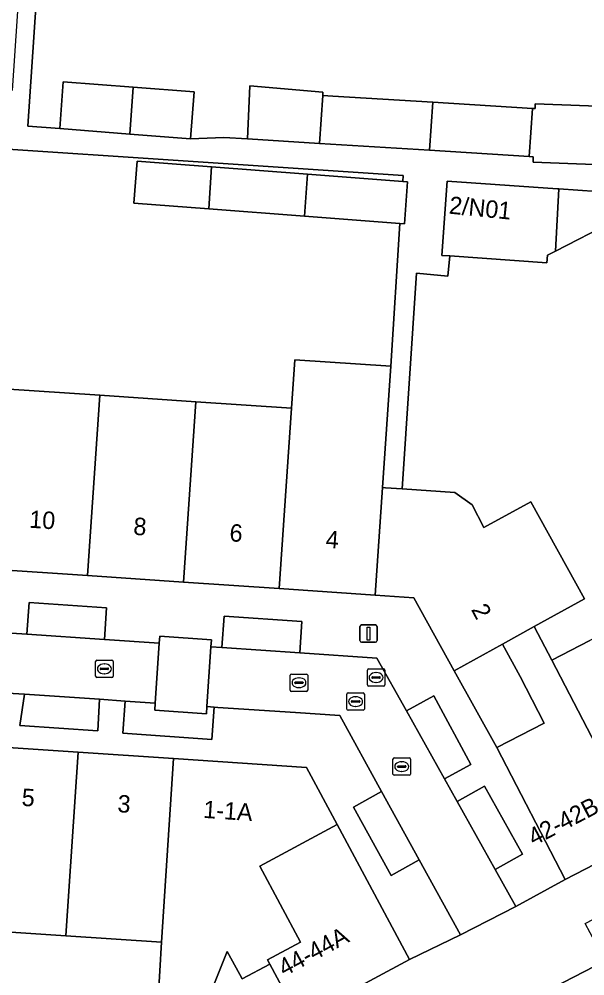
# Model space of a CAD drawing. Extents: x 159960 to 160866, y 382700 to 383354.
# Drawn here: x 160719.9 to 160752.4, y 382866.2 to 382921.1 of the extents above; entities that cross this region are included whole.
import ezdxf

# ---------------------------------------------------------------- set-up
doc = ezdxf.new("R2010")
doc.units = 0
for name, color, linetype in [('IMGEO_Erf', 7, 'Continuous'), ('IMGEO_Kolk', 7, 'Continuous'), ('IMGEO_Lichtmast', 7, 'Continuous'), ('IMGEO_Muur', 7, 'Continuous'), ('IMGEO_Pand', 7, 'Continuous'), ('IMGEO_Pand_nummerreeks', 7, 'Continuous'), ('IMGEO_Parkeervlak_open', 7, 'Continuous'), ('IMGEO_Rijbaan_lokaal_gesloten', 7, 'Continuous'), ('IMGEO_Rijbaan_lokaal_open', 7, 'Continuous'), ('IMGEO_Rioolput', 7, 'Continuous'), ('IMGEO_Voetpad_open', 7, 'Continuous')]:
    doc.layers.add(name, color=color, linetype=linetype)

msp = doc.modelspace()

# ---------------------------------------------------------------- linework, layer by layer
at = {"layer": 'IMGEO_Erf'}
for points in [[(160721.141, 382925.437), (160720.441, 382914.914), (160722.268, 382914.773), (160722.468, 382917.457), (160726.471, 382917.147), (160729.977, 382916.876), (160729.769, 382914.193), (160731.671, 382914.265), (160733.035, 382914.18), (160733.162, 382917.224), (160737.357, 382916.868), (160737.36, 382916.674), (160737.931, 382916.639), (160743.655, 382916.287), (160749.378, 382915.935), (160749.531, 382915.926), (160749.541, 382916.192), (160755.128, 382915.981)], [(160719.066, 382899.852), (160724.562, 382899.48), (160730.062, 382899.107), (160735.56, 382898.735), (160735.748, 382901.514), (160741.247, 382901.143), (160741.781, 382909.327), (160736.304, 382909.749), (160730.811, 382910.171), (160726.522, 382910.501), (160726.707, 382912.909), (160730.974, 382912.581), (160736.468, 382912.159), (160741.938, 382911.739), (160741.961, 382912.089), (160705.794, 382914.494)], [(160753.972, 382909.417), (160750.694, 382907.746), (160750.235, 382907.512), (160750.204, 382907.077), (160744.632, 382907.467), (160744.527, 382906.317), (160742.735, 382906.48), (160741.896, 382894.101), (160744.934, 382893.895), (160745.914, 382893.187), (160746.593, 382891.885), (160749.282, 382893.367), (160752.358, 382887.787), (160749.477, 382886.199), (160750.483, 382884.269), (160752.675, 382885.402)], [(160727.919, 382864.809), (160728.103, 382868.092), (160722.617, 382868.458), (160717.143, 382868.823), (160711.667, 382869.188), (160706.193, 382869.553), (160700.717, 382869.918), (160695.243, 382870.283), (160689.627, 382870.657), (160689.38, 382863.428)], [(160735.99, 382863.702), (160734.309, 382866.839), (160732.737, 382865.996), (160732.604, 382866.237), (160731.87, 382867.558), (160730.719, 382864.693)]]:
    msp.add_lwpolyline(points, dxfattribs=at)
msp.add_lwpolyline([(160747.334, 382879.263), (160750.054, 382880.669), (160748.677, 382883.335), (160747.652, 382885.194), (160744.889, 382883.671)], close=True, dxfattribs=at)
at = {"layer": 'IMGEO_Kolk'}
for p, q in [((160724.323, 382883.353), (160724.323, 382884.205)), ((160724.398, 382884.279), (160725.25, 382884.279)), ((160725.324, 382884.205), (160725.324, 382883.353)), ((160724.582, 382883.773), (160724.582, 382883.785)), ((160725.02, 382883.736), (160724.622, 382883.736)), ((160724.625, 382883.822), (160725.023, 382883.822)), ((160724.811, 382884.059), (160724.836, 382884.059)), ((160725.066, 382883.785), (160725.066, 382883.773)), ((160725.25, 382883.279), (160724.398, 382883.279)), ((160724.834, 382883.499), (160724.809, 382883.499)), ((160735.487, 382882.555), (160735.487, 382883.407)), ((160735.562, 382883.481), (160736.414, 382883.481)), ((160735.975, 382883.261), (160736, 382883.261)), ((160736.488, 382883.407), (160736.488, 382882.555)), ((160735.746, 382882.975), (160735.746, 382882.987)), ((160736.184, 382882.938), (160735.786, 382882.938)), ((160735.789, 382883.024), (160736.187, 382883.024)), ((160735.998, 382882.701), (160735.973, 382882.701)), ((160736.23, 382882.987), (160736.23, 382882.975)), ((160736.414, 382882.481), (160735.562, 382882.481)), ((160741.454, 382878.67), (160742.306, 382878.67)), ((160741.379, 382877.744), (160741.379, 382878.596)), ((160741.638, 382878.164), (160741.638, 382878.176)), ((160742.076, 382878.127), (160741.678, 382878.127)), ((160741.681, 382878.213), (160742.079, 382878.213)), ((160741.867, 382878.45), (160741.892, 382878.45)), ((160742.122, 382878.176), (160742.122, 382878.164)), ((160742.38, 382878.596), (160742.38, 382877.744)), ((160742.306, 382877.67), (160741.454, 382877.67)), ((160741.89, 382877.89), (160741.865, 382877.89))]:
    msp.add_line(p, q, dxfattribs=at)
for points in [[(160724.323, 382883.353), (160724.323, 382884.205)], [(160724.398, 382884.279), (160725.25, 382884.279)], [(160725.324, 382884.205), (160725.324, 382883.353)], [(160725.25, 382883.279), (160724.398, 382883.279)], [(160735.487, 382882.555), (160735.487, 382883.407)], [(160735.562, 382883.481), (160736.414, 382883.481)], [(160736.488, 382883.407), (160736.488, 382882.555)], [(160736.414, 382882.481), (160735.562, 382882.481)], [(160741.454, 382878.67), (160742.306, 382878.67)], [(160741.379, 382877.744), (160741.379, 382878.596)], [(160742.38, 382878.596), (160742.38, 382877.744)], [(160742.306, 382877.67), (160741.454, 382877.67)]]:
    msp.add_lwpolyline(points, dxfattribs=at)
for centre, radius, start, end in [((160724.4, 382884.203), 0.0765, 91.552, 178.448), ((160724.4, 382884.203), 0.0765, 91.552, 178.448), ((160725.248, 382884.203), 0.0765, 1.552, 88.448), ((160725.248, 382884.203), 0.0765, 1.552, 88.448), ((160724.622, 382883.782), 0.0403, 85.8775, 175.7526), ((160724.619, 382883.772), 0.0366, 178.938, 274.7102), ((160725.023, 382883.779), 0.043, 264.8664, 352.4533), ((160725.027, 382883.784), 0.0386, 1.7309, 96.639), ((160724.4, 382883.355), 0.0765, 181.552, 268.448), ((160724.4, 382883.355), 0.0765, 181.552, 268.448), ((160725.248, 382883.355), 0.0765, 271.552, 358.448), ((160725.248, 382883.355), 0.0765, 271.552, 358.448), ((160735.564, 382883.405), 0.0765, 91.552, 178.448), ((160735.564, 382883.405), 0.0765, 91.552, 178.448), ((160736.412, 382883.405), 0.0765, 1.552, 88.448), ((160736.412, 382883.405), 0.0765, 1.552, 88.448), ((160735.564, 382882.557), 0.0765, 181.552, 268.448), ((160735.564, 382882.557), 0.0765, 181.552, 268.448), ((160735.786, 382882.984), 0.0403, 85.8775, 175.7526), ((160735.783, 382882.974), 0.0366, 178.938, 274.7102), ((160736.187, 382882.981), 0.043, 264.8664, 352.4533), ((160736.191, 382882.986), 0.0386, 1.7309, 96.639), ((160736.412, 382882.557), 0.0765, 271.552, 358.448), ((160736.412, 382882.557), 0.0765, 271.552, 358.448), ((160741.456, 382878.594), 0.0765, 91.552, 178.448), ((160741.456, 382878.594), 0.0765, 91.552, 178.448), ((160742.304, 382878.594), 0.0765, 1.552, 88.448), ((160742.304, 382878.594), 0.0765, 1.552, 88.448), ((160741.678, 382878.173), 0.0403, 85.8775, 175.7526), ((160741.675, 382878.163), 0.0366, 178.938, 274.7102), ((160742.079, 382878.17), 0.043, 264.8664, 352.4533), ((160742.083, 382878.175), 0.0386, 1.7309, 96.639), ((160741.456, 382877.746), 0.0765, 181.552, 268.448), ((160741.456, 382877.746), 0.0765, 181.552, 268.448), ((160742.304, 382877.746), 0.0765, 271.552, 358.448), ((160742.304, 382877.746), 0.0765, 271.552, 358.448)]:
    msp.add_arc(centre, radius, start, end, dxfattribs=at)
for centre, major_axis, ratio, start_param, end_param in [((160724.81, 382883.779), (-0.387, 0.002), 0.722429, 4.712389, 7.853982), ((160724.835, 382883.779), (-0.39, 0.002), 0.717154, 1.570796, 4.712389), ((160735.974, 382882.981), (-0.387, 0.002), 0.722429, 4.712389, 7.853982), ((160735.999, 382882.981), (-0.39, 0.002), 0.717154, 1.570796, 4.712389), ((160741.866, 382878.17), (-0.387, 0.002), 0.722429, 4.712389, 7.853982), ((160741.891, 382878.17), (-0.39, 0.002), 0.717154, 1.570796, 4.712389)]:
    msp.add_ellipse(centre, major_axis=major_axis, ratio=ratio, start_param=start_param, end_param=end_param, dxfattribs=at)
at = {"layer": 'IMGEO_Lichtmast'}
for p, q in [((160739.481, 382885.401), (160739.481, 382886.201)), ((160739.481, 382886.201), (160739.481, 382885.401)), ((160739.581, 382886.301), (160740.371, 382886.301)), ((160740.371, 382886.301), (160739.581, 382886.301)), ((160740.471, 382886.201), (160740.471, 382885.401)), ((160740.471, 382885.401), (160740.471, 382886.201)), ((160740.371, 382885.301), (160739.581, 382885.301)), ((160739.581, 382885.301), (160740.371, 382885.301))]:
    msp.add_line(p, q, dxfattribs=at)
msp.add_lwpolyline([(160739.901, 382886.176), (160740.051, 382886.176), (160740.051, 382885.426), (160739.901, 382885.426), (160739.901, 382886.176)], dxfattribs=at)
for centre, start, end in [((160739.581, 382886.201), 90, 180), ((160739.581, 382886.201), 90, 180), ((160740.371, 382886.201), 0, 90), ((160740.371, 382886.201), 360, 90), ((160739.581, 382885.401), 180, 270), ((160739.581, 382885.401), 180, 270), ((160740.371, 382885.401), 270, 0), ((160740.371, 382885.401), 270, 0)]:
    msp.add_arc(centre, 0.1, start, end, dxfattribs=at)
at = {"layer": 'IMGEO_Muur'}
msp.add_lwpolyline([(160744.889, 382883.671), (160747.334, 382879.263)], dxfattribs=at)
at = {"layer": 'IMGEO_Pand'}
for points in [[(160726.471, 382917.147), (160722.468, 382917.457), (160722.268, 382914.773), (160726.287, 382914.462)], [(160726.471, 382917.147), (160726.287, 382914.462), (160729.769, 382914.193), (160729.977, 382916.876)], [(160737.36, 382916.674), (160737.357, 382916.868), (160733.162, 382917.224), (160733.035, 382914.18), (160737.171, 382913.923)], [(160743.655, 382916.287), (160737.931, 382916.639), (160737.36, 382916.674), (160737.171, 382913.923), (160743.466, 382913.53)], [(160749.378, 382915.935), (160743.655, 382916.287), (160743.466, 382913.53), (160749.189, 382913.173)], [(160755.168, 382915.732), (160755.177, 382915.979), (160755.128, 382915.981), (160749.541, 382916.192), (160749.531, 382915.926), (160749.378, 382915.935), (160749.189, 382913.173), (160749.426, 382913.158), (160749.414, 382912.849), (160754.899, 382912.642), (160755.05, 382912.636), (160755.064, 382913.004)], [(160730.974, 382912.581), (160726.707, 382912.909), (160726.522, 382910.501), (160730.811, 382910.171)], [(160736.468, 382912.159), (160730.974, 382912.581), (160730.811, 382910.171), (160736.304, 382909.749)], [(160741.938, 382911.739), (160736.468, 382912.159), (160736.304, 382909.749), (160741.781, 382909.327), (160742.034, 382909.308), (160742.22, 382911.717)], [(160750.89, 382911.317), (160750.809, 382911.322), (160744.48, 382911.765), (160744.181, 382907.498), (160744.632, 382907.467), (160750.204, 382907.077), (160750.235, 382907.512), (160750.694, 382907.746)], [(160753.144, 382911.043), (160753.077, 382911.174), (160750.89, 382911.317), (160750.694, 382907.746), (160753.972, 382909.417)], [(160740.776, 382894.177), (160741.059, 382898.363), (160741.247, 382901.143), (160735.748, 382901.514), (160735.56, 382898.735), (160734.86, 382888.38), (160740.359, 382888.008)], [(160724.562, 382899.48), (160719.066, 382899.852), (160718.365, 382889.497), (160723.863, 382889.125)], [(160730.062, 382899.107), (160724.562, 382899.48), (160723.863, 382889.125), (160729.362, 382888.752)], [(160730.062, 382899.107), (160729.362, 382888.752), (160734.86, 382888.38), (160735.56, 382898.735)], [(160749.282, 382893.367), (160746.593, 382891.885), (160745.914, 382893.187), (160744.934, 382893.895), (160741.896, 382894.101), (160740.952, 382894.165), (160740.776, 382894.177), (160740.359, 382888.008), (160742.582, 382887.857), (160744.889, 382883.671), (160747.652, 382885.194), (160749.477, 382886.199), (160752.358, 382887.787)], [(160754.974, 382886.591), (160752.675, 382885.402), (160750.483, 382884.269), (160755.802, 382874.049), (160760.296, 382876.372), (160756.134, 382884.362)], [(160747.652, 382885.194), (160748.677, 382883.335), (160750.054, 382880.669), (160747.334, 382879.263), (160751.248, 382871.695), (160755.802, 382874.049), (160750.483, 382884.269), (160749.477, 382886.199)], [(160717.845, 382879.359), (160717.143, 382868.823), (160722.617, 382868.458), (160723.32, 382878.994)], [(160728.103, 382868.092), (160728.795, 382878.629), (160723.32, 382878.994), (160722.617, 382868.458)], [(160733.738, 382872.46), (160738.179, 382874.84), (160736.42, 382878.121), (160728.795, 382878.629), (160728.103, 382868.092), (160727.919, 382864.809), (160730.719, 382864.693), (160731.87, 382867.558), (160732.604, 382866.237), (160732.737, 382865.996), (160734.309, 382866.839), (160734.179, 382867.081), (160736.076, 382868.097)], [(160738.179, 382874.84), (160733.738, 382872.46), (160736.076, 382868.097), (160734.179, 382867.081), (160734.309, 382866.839), (160735.99, 382863.702), (160742.328, 382867.099)]]:
    msp.add_lwpolyline(points, close=True, dxfattribs=at)
at = {"layer": 'IMGEO_Parkeervlak_open'}
for points in [[(160724.823, 382885.459), (160724.941, 382887.281), (160720.506, 382887.591), (160720.375, 382885.764)], [(160731.571, 382884.997), (160736.035, 382884.692), (160736.158, 382886.502), (160731.705, 382886.809)], [(160720.242, 382882.32), (160719.985, 382880.529), (160724.442, 382880.214), (160724.54, 382882.029)], [(160742.152, 382881.365), (160744.329, 382877.473), (160745.846, 382878.299), (160743.714, 382882.23)], [(160731.113, 382881.583), (160730.703, 382881.611), (160730.675, 382881.202), (160727.712, 382881.403), (160727.74, 382881.812), (160726.017, 382881.929), (160725.89, 382880.081), (160730.996, 382879.723)], [(160745.057, 382876.172), (160747.244, 382872.263), (160748.814, 382873.145), (160746.637, 382877.041)], [(160740.724, 382876.741), (160739.115, 382875.836), (160741.27, 382871.925), (160742.88, 382872.82)]]:
    msp.add_lwpolyline(points, close=True, dxfattribs=at)
at = {"layer": 'IMGEO_Rijbaan_lokaal_gesloten'}
msp.add_lwpolyline([(160658.793, 382788.217), (160658.795, 382788.219), (160713.681, 382839.487), (160716.862, 382842.261), (160724.646, 382848.459), (160727.703, 382850.736), (160730.902, 382852.951), (160733.843, 382854.844), (160736.572, 382856.486), (160745.822, 382861.534), (160754.189, 382865.798), (160800.497, 382890.041), (160850.387, 382917.788), (160851.212, 382918.383), (160851.951, 382919.185), (160852.601, 382920.321), (160849.639, 382918.958), (160833.656, 382910.101), (160799.878, 382891.281), (160796.345, 382889.412), (160753.546, 382867.025), (160745.141, 382862.692), (160736.087, 382857.81)], dxfattribs=at)
at = {"layer": 'IMGEO_Rijbaan_lokaal_open'}
msp.add_lwpolyline([(160718.623, 382882.426), (160720.242, 382882.32), (160724.54, 382882.029), (160726.017, 382881.929), (160727.74, 382881.812), (160727.972, 382885.244), (160724.823, 382885.459), (160720.375, 382885.764), (160718.9, 382885.865)], dxfattribs=at)
for points in [[(160727.74, 382881.812), (160727.712, 382881.403), (160730.675, 382881.202), (160730.703, 382881.611), (160730.935, 382885.041), (160730.963, 382885.45), (160728, 382885.652), (160727.972, 382885.244)], [(160731.113, 382881.583), (160731.339, 382881.568), (160735.778, 382881.268), (160738.329, 382881.095), (160740.724, 382876.741), (160742.88, 382872.82), (160745.251, 382868.51), (160748.426, 382870.149), (160747.244, 382872.263), (160745.057, 382876.172), (160744.329, 382877.473), (160742.152, 382881.365), (160740.46, 382884.389), (160736.035, 382884.692), (160731.571, 382884.997), (160730.935, 382885.041), (160730.703, 382881.611)]]:
    msp.add_lwpolyline(points, close=True, dxfattribs=at)
at = {"layer": 'IMGEO_Rioolput'}
for p, q in [((160739.908, 382882.855), (160739.908, 382883.707)), ((160739.983, 382883.781), (160740.835, 382883.781)), ((160740.909, 382883.707), (160740.909, 382882.855)), ((160740.167, 382883.275), (160740.167, 382883.287)), ((160740.605, 382883.238), (160740.207, 382883.238)), ((160740.21, 382883.324), (160740.608, 382883.324)), ((160740.396, 382883.561), (160740.421, 382883.561)), ((160740.651, 382883.287), (160740.651, 382883.275)), ((160740.835, 382882.781), (160739.983, 382882.781)), ((160740.419, 382883.001), (160740.394, 382883.001)), ((160738.736, 382881.474), (160738.736, 382882.326)), ((160738.811, 382882.4), (160739.663, 382882.4)), ((160739.224, 382882.18), (160739.249, 382882.18)), ((160739.737, 382882.326), (160739.737, 382881.474)), ((160738.995, 382881.894), (160738.995, 382881.906)), ((160739.433, 382881.857), (160739.035, 382881.857)), ((160739.038, 382881.943), (160739.436, 382881.943)), ((160739.247, 382881.62), (160739.222, 382881.62)), ((160739.479, 382881.906), (160739.479, 382881.894)), ((160739.663, 382881.4), (160738.811, 382881.4))]:
    msp.add_line(p, q, dxfattribs=at)
for points in [[(160739.908, 382882.855), (160739.908, 382883.707)], [(160739.983, 382883.781), (160740.835, 382883.781)], [(160740.909, 382883.707), (160740.909, 382882.855)], [(160740.835, 382882.781), (160739.983, 382882.781)], [(160738.736, 382881.474), (160738.736, 382882.326)], [(160738.811, 382882.4), (160739.663, 382882.4)], [(160739.737, 382882.326), (160739.737, 382881.474)], [(160739.663, 382881.4), (160738.811, 382881.4)]]:
    msp.add_lwpolyline(points, dxfattribs=at)
for centre, radius, start, end in [((160739.985, 382883.705), 0.0765, 91.552, 178.448), ((160739.985, 382883.705), 0.0765, 91.552, 178.448), ((160740.833, 382883.705), 0.0765, 1.552, 88.448), ((160740.833, 382883.705), 0.0765, 1.552, 88.448), ((160740.207, 382883.284), 0.0403, 85.8775, 175.7526), ((160740.204, 382883.274), 0.0366, 178.938, 274.7102), ((160740.608, 382883.281), 0.043, 264.8664, 352.4533), ((160740.612, 382883.286), 0.0386, 1.7309, 96.639), ((160739.985, 382882.857), 0.0765, 181.552, 268.448), ((160739.985, 382882.857), 0.0765, 181.552, 268.448), ((160740.833, 382882.857), 0.0765, 271.552, 358.448), ((160740.833, 382882.857), 0.0765, 271.552, 358.448), ((160738.813, 382882.324), 0.0765, 91.552, 178.448), ((160738.813, 382882.324), 0.0765, 91.552, 178.448), ((160739.661, 382882.324), 0.0765, 1.552, 88.448), ((160739.661, 382882.324), 0.0765, 1.552, 88.448), ((160738.813, 382881.476), 0.0765, 181.552, 268.448), ((160738.813, 382881.476), 0.0765, 181.552, 268.448), ((160739.035, 382881.903), 0.0403, 85.8775, 175.7526), ((160739.032, 382881.893), 0.0366, 178.938, 274.7102), ((160739.436, 382881.9), 0.043, 264.8664, 352.4533), ((160739.44, 382881.905), 0.0386, 1.7309, 96.639), ((160739.661, 382881.476), 0.0765, 271.552, 358.448), ((160739.661, 382881.476), 0.0765, 271.552, 358.448)]:
    msp.add_arc(centre, radius, start, end, dxfattribs=at)
for centre, major_axis, ratio, start_param, end_param in [((160740.395, 382883.281), (-0.387, 0.002), 0.722429, 4.712389, 7.853982), ((160740.42, 382883.281), (-0.39, 0.002), 0.717154, 1.570796, 4.712389), ((160739.223, 382881.9), (-0.387, 0.002), 0.722429, 4.712389, 7.853982), ((160739.248, 382881.9), (-0.39, 0.002), 0.717154, 1.570796, 4.712389)]:
    msp.add_ellipse(centre, major_axis=major_axis, ratio=ratio, start_param=start_param, end_param=end_param, dxfattribs=at)
at = {"layer": 'IMGEO_Voetpad_open'}
for points in [[(160780.853, 382915.102), (160775.97, 382914.827), (160772.269, 382914.505), (160766.454, 382913.997), (160760.752, 382913.5), (160755.064, 382913.004), (160755.05, 382912.636), (160754.899, 382912.642), (160749.414, 382912.849), (160749.426, 382913.158), (160749.189, 382913.173), (160743.466, 382913.53), (160737.171, 382913.923), (160733.035, 382914.18), (160731.671, 382914.265), (160729.769, 382914.193), (160726.287, 382914.462), (160722.268, 382914.773), (160720.441, 382914.914), (160721.141, 382925.437), (160722.012, 382938.523), (160720.984, 382938.591), (160720.113, 382925.505), (160719.544, 382916.968)], [(160705.794, 382914.494), (160741.961, 382912.089), (160741.938, 382911.739), (160742.22, 382911.717), (160742.034, 382909.308), (160741.781, 382909.327), (160741.247, 382901.143), (160741.059, 382898.363), (160740.776, 382894.177), (160740.952, 382894.165), (160741.896, 382894.101), (160742.735, 382906.48), (160744.527, 382906.317), (160744.632, 382907.467), (160744.181, 382907.498), (160744.48, 382911.765), (160750.809, 382911.322), (160750.89, 382911.317), (160753.077, 382911.174)], [(160745.141, 382862.692), (160753.546, 382867.025), (160752.41, 382869.16), (160764.501, 382875.466), (160764.088, 382876.287), (160766.431, 382877.558), (160766.867, 382876.685), (160782.488, 382884.866), (160782.238, 382885.343), (160784.415, 382886.467), (160784.66, 382886.011), (160799.77, 382893.981), (160799.467, 382894.398), (160801.958, 382895.604), (160802.069, 382895.291), (160832.466, 382912.232)], [(160718.9, 382885.865), (160720.375, 382885.764), (160720.506, 382887.591), (160724.941, 382887.281), (160724.823, 382885.459), (160727.972, 382885.244), (160728, 382885.652), (160730.963, 382885.45), (160730.935, 382885.041), (160731.571, 382884.997), (160731.705, 382886.809), (160736.158, 382886.502), (160736.035, 382884.692), (160740.46, 382884.389), (160742.152, 382881.365), (160743.714, 382882.23), (160745.846, 382878.299), (160744.329, 382877.473), (160745.057, 382876.172), (160746.637, 382877.041), (160748.814, 382873.145), (160747.244, 382872.263), (160748.426, 382870.149), (160751.248, 382871.695), (160747.334, 382879.263), (160744.889, 382883.671), (160742.582, 382887.857), (160740.359, 382888.008), (160734.86, 382888.38), (160729.362, 382888.752), (160723.863, 382889.125), (160718.365, 382889.497)], [(160779.747, 382886.324), (160778.04, 382885.442), (160775.979, 382884.377), (160775.295, 382884.595), (160773.38, 382883.605), (160771.194, 382882.476), (160770.973, 382881.779), (160769.194, 382880.86), (160767.204, 382879.832), (160766.453, 382880.071), (160764.511, 382879.067), (160762.058, 382877.798), (160761.861, 382877.181), (160760.296, 382876.372), (160755.802, 382874.049), (160751.248, 382871.695), (160748.426, 382870.149), (160745.251, 382868.51), (160742.328, 382867.099), (160735.99, 382863.702)], [(160717.845, 382879.359), (160723.32, 382878.994), (160728.795, 382878.629), (160736.42, 382878.121), (160738.179, 382874.84), (160742.328, 382867.099), (160745.251, 382868.51), (160742.88, 382872.82), (160741.27, 382871.925), (160739.115, 382875.836), (160740.724, 382876.741), (160738.329, 382881.095), (160735.778, 382881.268), (160731.339, 382881.568), (160731.113, 382881.583), (160730.996, 382879.723), (160725.89, 382880.081), (160726.017, 382881.929), (160724.54, 382882.029), (160724.442, 382880.214), (160719.985, 382880.529), (160720.242, 382882.32), (160718.623, 382882.426)]]:
    msp.add_lwpolyline(points, dxfattribs=at)

# ---------------------------------------------------------------- texts
at = {"layer": 'IMGEO_Pand_nummerreeks'}
for s, rotation, p in [('2/N01', 354.385, (160744.563, 382909.898)), ('10', 356.1252, (160720.489, 382891.879)), ('8', 356.1252, (160726.465, 382891.474)), ('6', 356.1252, (160731.978, 382891.101)), ('4', 356.1268, (160737.497, 382890.728)), ('2', 298.0117, (160745.841, 382887.18)), ('5', 356.186, (160720.057, 382875.924)), ('3', 356.186, (160725.554, 382875.558)), ('1-1A', 356.1898, (160730.475, 382875.23)), ('42-42B', 27.3348, (160749.455, 382873.605)), ('44-44A', 28.1895, (160735.143, 382866.108))]:
    msp.add_text(s, height=1, rotation=rotation, dxfattribs=at).set_placement(p)

doc.saveas('drawing.dxf')
